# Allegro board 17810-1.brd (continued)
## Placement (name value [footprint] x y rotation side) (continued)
Q1801  2N7002KDW-1-GP  [SOT-363H44]  101.62 16.02 90 bottom
Q2001  PJT138KA-GP  [SOT-363H44]  150.49 27.25 180 bottom
Q2408  2N7002K-2-GP  [SOT23DGS2D4H44]  191.49 39.11 0 bottom
Q2414  2N7002K-2-GP  [SOT23DGS2D4H44]  187.27 35.12 180 bottom
Q2415  2N7002K-2-GP  [SOT23DGS2D4H44]  190.93 35.42 90 bottom
Q2416  2N7002KDW-1-GP  [SOT-363H44]  180.95 47.54 0 top
Q2417  2N7002K-2-GP  [SOT23DGS2D4H44]  188.64 9.87 180 bottom
Q2503  2N7002KDW-1-GP  [SOT-363H44]  141.2 10.43 270 bottom
Q2601  2N7002KDW-1-GP  [SOT-363H44]  134.77 32.76 90 bottom
Q2602  2N7002K-2-GP  [SOT23DGS2D4H44]  142.64 23.69 180 bottom
Q2603  PMBS3904-1-GP  [SOT-23-10H44]  49.5 96.38 90 bottom
Q2605  2N7002KDW-GP  [SOT-363H44]  196.04 36.64 0 bottom
Q2701  2N7002K-2-GP  [SOT23DGS2D4H44]  21.64 29.96 270 bottom
Q2702  DMG3415U-GP  [SOT23DGS2D4H48]  21.64 26.41 90 bottom
Q3701  2N7002K-2-GP  [SOT23DGS2D4H44]  23.42 98.09 0 top
Q5704  2N7002KDW-1-GP  [SOT-363H44]  18.62 61.71 0 bottom
Q6401  LDTA144VLT1G-GP  [SOT23CBE2D4H44]  53.39 7.84 270 bottom
Q6402  LDTA144VLT1G-GP  [SOT23CBE2D4H44]  69.62 15.1 270 bottom
Q6403  PJA138KA-GP  [SOT23DGS2D4H44]  177.54 48.45 270 top
Q6501  DMN3404L-7-1-GP  [SOT23DGS2D4H44]  113.28 10.3 270 bottom
Q6502  DMG3415U-GP  [SOT23DGS2D4H48]  141.63 14.22 270 bottom
Q6503  2N7002K-2-GP  [SOT23DGS2D4H44]  141.27 18.25 180 bottom
Q6504  2N7002KDW-1-GP  [SOT-363H44]  136.19 21.86 270 bottom
Q6505  LDTA144VLT1G-GP  [SOT23CBE2D4H44]  147.22 21.51 90 bottom
Q7001  2N7002KDW-1-GP  [SOT-363H44]  148 11.4 180 bottom
Q9102  DMP2130L-7-GP  [SOT23DGS2D4H48]  28.67 19.52 90 bottom
Q9104  SSM3K15AMFV-GP-U  [SOT723DGS1D2H22]  33.83 22.83 90 top
R401  1KR2J-1-GP  [R402H16]  131.14 76.98 270 bottom
R402  51R2J-2-GP  [R402H16]  133.02 70.45 180 bottom
R403  499R2F-2-GP  [R402H16]  130.58 76.14 90 bottom
R404  100KR2J-1-GP  [R402H16]  121.64 13.99 90 bottom
R406  51R2J-2-GP  [R402H16]  131.14 72.33 270 bottom
R407  51R2J-2-GP  [R402H16]  123.9 69.03 0 top
R408  51R2J-2-GP  [R402H16]  131.16 67.1 270 bottom
R409  51R2J-2-GP  [R402H16]  131.47 66.29 270 bottom
R410  -  [0R0402-PAD]  120.32 12.67 0 bottom
R412  49D9R2F-GP  [R402H16]  93.9 51.45 270 top
R413  49D9R2F-GP  [R402H16]  94.38 53.18 270 top
R414  49D9R2F-GP  [R402H16]  120.9 74.85 180 top
R415  49D9R2F-GP  [R402H16]  120.9 73.14 180 top
R416  51R2J-2-GP  [R402H16]  131.14 68.72 270 bottom
R417  1KR2J-1-GP  [R402H16]  131.16 67.91 270 bottom
R419  1KR2J-1-GP  [R402H16]  133.45 75.23 90 bottom
R421  51R2J-2-GP  [R402H16]  131.19 70.7 270 bottom
R422  51R2J-2-GP  [R402H16]  131.47 65.47 270 bottom
R423  51R2J-2-GP  [R402H16]  131.14 71.52 270 bottom
R501  121R2F-GP  [R402H16]  94.36 54.91 270 top
R502  80D6R2F-L-GP  [R402H16]  94.36 54.02 270 top
R503  100R2F-L1-GP-U  [R402H14]  93.9 52.32 270 top
R504  -  [0R0402-PAD]  88.44 18.25 270 top
R505  470R2F-GP  [R402H16]  88.44 16.35 90 top
R506  220KR2F-GP  [R402H16]  30.53 9.74 270 bottom
R601  49D9R2F-GP  [R402H16]  121.46 70.45 180 top
R602  -  [0R0402-PAD]  94.41 79.47 270 top
R603  100KR2J-1-GP  [R402H16]  133.48 76.06 270 bottom
R604  1KR2J-1-GP  [R402H16]  131.16 77.82 270 bottom
R605  1KR2J-1-GP  [R402H16]  122.32 76.9 0 top
R703  -  [0R0603-PAD]  123.7 44.64 0 top
R705  -  [0R0805-PAD]  94.38 57.09 0 top
R706  D0002R5J-GP-U  [R805H20]  119.3 64.99 180 top
R707  D0002R5J-GP-U  [R805H20]  119.23 60.98 180 top
R708  D0002R5J-GP-U  [R805H20]  112.32 60.93 180 top
R709  -  [0R0402-PAD]  133.45 71.75 270 bottom
R712  0R2J-2-GP  [R402H16]  121.46 66.54 180 top
R719  100R2F-L1-GP-U  [R402H14]  121.92 54.8 90 top
R720  100R2F-L1-GP-U  [R402H14]  121.92 55.57 270 top
R721  100R2F-L1-GP-U  [R402H14]  119.56 77.44 90 top
R722  100R2F-L1-GP-U  [R402H14]  120.98 77.11 0 top
R723  54D9R2F-L1-GP  [R402H16]  133.45 73.5 90 bottom
R726  100R2F-L1-GP-U  [R402H14]  133.48 72.64 90 bottom
R727  56R2J-4-GP  [R402H16]  133.45 74.36 90 bottom
R728  220R2J-L2-GP  [R402H16]  131.11 74.16 90 bottom
R732  -  [0R0402-PAD]  131.11 73.35 270 bottom
R734  100R2F-L1-GP-U  [R402H14]  121.49 49.75 180 top
R735  100R2F-L1-GP-U  [R402H14]  123.49 48.61 270 top
R801  24D9R2F-L-GP  [R402H16]  121.46 64.61 180 top
R802  10KR2J-3-GP  [R402H16]  119.1 28.77 180 bottom
R803  100KR2J-1-GP  [R402H16]  121.92 27.68 90 bottom
R804  0R2J-2-GP  [R402H16]  121.26 26.86 90 bottom
R1101  -  [0R1206-PAD]  93.01 16.73 0 bottom
R1102  -  [0R0603-PAD]  120.98 35.86 270 top
R1103  -  [0R0603-PAD]  108.68 37.81 90 top
R1104  -  [0R0603-PAD]  111.66 36.88 90 top
R1204  10KR2F-L1-GP  [R402H15]  68.38 22.44 90 top
R1205  -  [0R0402-PAD]  66.67 22.44 90 top
R1206  2R2F-GP  [R402H16]  72.62 48.04 90 top
R1208  10KR2F-L1-GP  [R402H15]  68.38 21.63 90 top
R1209  24D9R2F-L-GP  [R402H16]  72.6 49.81 90 top
R1210  -  [0R0402-PAD]  66.04 20.08 90 top
R1211  10KR2F-L1-GP  [R402H15]  62.3 44.34 270 top
R1212  -  [0R0402-PAD]  63.98 44.34 270 top
R1215  240R2F-1-GP  [R402H16]  64.08 52.59 0 top
R1216  SC2D2U10V3KX-L-GP  [C603H36]  50.95 26.74 270 top
R1302  10KR2F-L1-GP  [R402H15]  54.84 22.52 90 top
R1303  -  [0R0402-PAD]  53.11 22.52 90 top
R1305  2R2F-GP  [R402H16]  50.85 43.15 270 top
R1306  10KR2F-2-GP  [R402H16]  55.8 24.07 90 top
R1307  0R2J-L-GP  [R402H15]  54.05 24.1 270 top
R1309  24D9R2F-L-GP  [R402H16]  50.6 45.05 270 top
R1310  10KR2F-L1-GP  [R402H15]  48.46 46.4 180 top
R1311  -  [0R0402-PAD]  49.76 45.94 90 top
R1312  240R2F-1-GP  [R402H16]  51.31 55.87 270 top
R1501  100R2F-L1-GP-U  [R402H14]  123.32 42.51 270 top
R1502  200R2F-L-GP  [R402H16]  108.7 36.8 90 top
R1503  10KR2J-3-GP  [R402H16]  129.84 39.39 90 bottom
R1603  113R2F-GP  [R402H16]  115.21 38.7 90 top
R1604  100R2F-L1-GP-U  [R402H14]  122.6 38.8 90 top
R1606  10KR2J-3-GP  [R402H16]  120.67 28.24 0 bottom
R1607  10KR2J-3-GP  [R402H16]  87.02 21.84 90 top
R1608  10KR2J-3-GP  [R402H16]  119.86 28.24 0 bottom
R1701  10KR2J-3-GP  [R402H16]  117.42 43.25 90 top
R1702  1KR2J-1-GP  [R402H16]  150.42 19.02 270 top
R1704  -  [0R0402-PAD]  100.38 18.25 270 bottom
R1706  -  [0R0402-PAD]  102.08 18.25 90 bottom
R1707  10KR2J-3-GP  [R402H16]  59.74 15.46 180 bottom
R1708  -  [0R0402-PAD]  111.1 23.54 180 bottom
R1711  -  [0R0603-PAD]  58.72 15.84 180 bottom
R1713  -  [0R0402-PAD]  113.56 23.74 90 bottom
R1714  10KR2J-3-GP  [R402H16]  133.04 77.33 0 bottom
R1715  100KR2J-1-GP  [R402H16]  114.91 23.18 180 bottom
R1716  100KR2F-L1-GP  [R402H16]  106.6 93.82 180 bottom
R1717  100KR2J-1-GP  [R402H16]  123.47 37.13 270 top
R1718  0R2J-2-GP  [R402H16]  103.78 18.25 270 bottom
R1719  47KR2F-GP  [R402H16]  105.84 93.82 0 bottom
R1720  -  [0R0402-PAD]  150.42 18 90 top
R1724  0R6J-L-GP  [R1206H26]  97.69 14.95 0 bottom
R1726  10KR2J-3-GP  [R402H16]  150.85 13.48 270 bottom
R1727  100KR2J-1-GP  [R402H16]  152.55 13.48 270 bottom
R1728  -  [0R0402-PAD]  151.56 15.84 270 top
R1730  330KR2J-L1-GP  [R402H16]  96.24 22.62 180 top
R1731  20KR2J-L2-GP  [R402H16]  110.75 39.67 180 top
R1732  0R2J-2-GP  [R402H16]  60.5 15.46 0 bottom
R1737  100KR2J-1-GP  [R402H16]  152.8 20.13 90 top
R1739  10KR2J-3-GP  [R402H16]  109.27 25.37 270 bottom
R1802  1MR2J-1-GP  [R402H16]  131.93 50.72 180 bottom
R1803  2K7R2F-GP  [R402H16]  119.38 49.06 0 top
R1804  0R2J-2-GP  [R402H16]  131.16 52.39 0 bottom
R1805  0R2J-2-GP  [R402H16]  131.16 50.72 0 bottom
R1806  15R2F-2-GP  [R402H16]  89.08 30.19 0 top
R1807  0R2J-2-GP  [R402H16]  94.28 49.37 90 top
R1808  0R2J-2-GP  [R402H16]  115.24 18.76 180 bottom
R1811  10R2F-L-GP  [R402H14]  94.44 28.64 90 top
R1812  -  [0R0402-PAD]  94.44 27.65 90 top
R1815  10MR2J-L-GP  [R402H16]  99.52 22.85 180 bottom
R1818  8K2R2F-1-GP  [R402H16]  106.98 25.24 0 bottom
R1820  10KR2J-3-GP  [R402H16]  97.94 22.37 180 top
R1821  10KR2J-3-GP  [R402H16]  97.1 22.39 180 top
R1822  1KR2J-1-GP  [R402H16]  113.26 25.01 180 bottom
R1823  1KR2J-1-GP  [R402H16]  112.01 25.14 90 bottom
R1824  1KR2J-1-GP  [R402H16]  94.89 33.8 180 top
R1825  1KR2J-1-GP  [R402H16]  94.46 32.53 90 top
R1826  0R2J-2-GP  [R402H16]  107.47 32.43 270 bottom
R1827  10KR2J-3-GP  [R402H16]  94.41 41.62 90 top
R1828  10KR2J-3-GP  [R402H16]  94.41 39.34 90 top
R1836  2K2R2J-2-GP  [R402H16]  114.07 25.44 180 bottom
R1837  150KR2J-GP  [R402H16]  108.76 38.83 90 top
R1901  200R2F-L-GP  [R402H16]  115.28 39.46 90 top
R1908  -  [0R0402-PAD]  93.62 46.83 90 top
R1909  1KR2J-1-GP  [R402H16]  91.11 49.5 90 top
R1912  10KR2J-3-GP  [R402H16]  124.89 21.43 0 top
R1913  10KR2J-3-GP  [R402H16]  123.75 22.19 0 top
R1914  10KR2J-3-GP  [R402H16]  115.16 19.68 0 top
R1915  10KR2J-3-GP  [R402H16]  114.37 19.68 180 top
R1916  10KR2J-3-GP  [R402H16]  113.59 20.92 90 top
R1917  10KR2J-3-GP  [R402H16]  113.08 22.19 0 top
R1918  10KR2J-3-GP  [R402H16]  109.52 21.05 270 top
R1919  10KR2J-3-GP  [R402H16]  111.68 22.55 270 top
R1920  10KR2J-3-GP  [R402H16]  109.17 22.32 0 top
R1921  10KR2J-3-GP  [R402H16]  108.35 22.32 180 top
R2001  10KR2J-3-GP  [R402H16]  148.69 23.99 270 bottom
R2003  0R2J-2-GP  [R402H16]  110.67 27.4 0 bottom
R2004  0R2J-2-GP  [R402H16]  109.85 27.58 0 bottom
R2005  10KR2J-3-GP  [R402H16]  112.09 29.81 180 bottom
R2006  1KR2J-1-GP  [R402H16]  94.36 37.05 90 top
R2007  1KR2J-1-GP  [R402H16]  109.78 20.36 0 bottom
R2008  10KR2J-3-GP  [R402H16]  110.31 29.02 90 bottom
R2009  10KR2J-3-GP  [R402H16]  113.36 32.12 270 bottom
R2010  10KR2J-3-GP  [R402H16]  112.9 30.88 0 bottom
R2019  1KR2J-1-GP  [R402H16]  110.54 20.36 180 bottom
R2020  0R2J-2-GP  [R402H16]  117.17 23.97 180 bottom
R2021  0R2J-2-GP  [R402H16]  118.03 23.97 180 bottom
R2023  0R2J-2-GP  [R402H16]  94.49 23.28 90 top
R2024  0R2J-2-GP  [R402H16]  94.79 24.1 90 top
R2025  0R2J-2-GP  [R402H16]  94.84 25.72 90 top
R2026  0R2J-2-GP  [R402H16]  94.79 24.91 90 top
R2027  0R2J-2-GP  [R402H16]  94.84 26.53 90 top
R2028  0R2J-2-GP  [R402H16]  102.28 20.03 180 bottom
R2029  10KR2J-3-GP  [R402H16]  109.4 30.24 0 bottom
R2030  10KR2J-3-GP  [R402H16]  108.63 30.88 180 bottom
R2031  100KR2J-1-GP  [R402H16]  91.24 25.37 270 top
R2032  100KR2J-1-GP  [R402H16]  91.24 26.25 270 top
R2033  100KR2J-1-GP  [R402H16]  91.24 27.02 270 top
R2034  100KR2J-1-GP  [R402H16]  103.55 21.3 90 top
R2035  100KR2J-1-GP  [R402H16]  91.24 27.78 270 top
R2036  100KR2J-1-GP  [R402H16]  91.24 28.54 270 top
R2040  10KR2J-3-GP  [R402H16]  114.07 27.12 0 bottom
R2041  10KR2J-3-GP  [R402H16]  109.02 20.36 0 bottom
R2042  10KR2J-3-GP  [R402H16]  122.81 24.38 180 bottom
R2043  10KR2J-3-GP  [R402H16]  108.25 20.03 0 bottom
R2044  10KR2J-3-GP  [R402H16]  112.11 31.67 0 bottom
R2045  10KR2J-3-GP  [R402H16]  121.59 22.7 90 top
R2046  10KR2J-3-GP  [R402H16]  114.73 31.59 0 bottom
R2047  10KR2J-3-GP  [R402H16]  115.49 31.59 0 bottom
R2048  51KR2J-1-GP  [R402H16]  110.92 30.24 0 bottom
R2049  51KR2J-1-GP  [R402H16]  110.16 30.24 0 bottom
R2050  10KR2J-3-GP  [R402H16]  148.59 25.21 180 bottom
R2055  150KR2J-GP  [R402H16]  107.87 30.88 0 bottom
R2056  20KR2J-L2-GP  [R402H16]  108.68 32.76 0 bottom
R2101  -  [0R0402-PAD]  69.9 18.51 270 top
R2102  0R2J-2-GP  [R402H16]  67.61 17.49 90 top
R2106  -  [0R0603-PAD]  76.43 16.93 0 top
R2107  -  [0R0603-PAD]  120.11 38.55 90 top
R2108  -  [0R0603-PAD]  115.11 42.19 0 top
R2109  -  [0R0603-PAD]  134.8 41.88 270 bottom
R2110  -  [0R0603-PAD]  134.8 44.42 270 bottom
R2111  -  [0R0603-PAD]  134.8 43.15 270 bottom
R2201  1MR2J-1-GP  [R402H16]  131.8 36.08 180 bottom
R2202  0R2J-2-GP  [R402H16]  130.58 36.44 90 bottom
R2203  0R2J-2-GP  [R402H16]  130.58 35.65 90 bottom
R2402  -  [0R0402-PAD]  177.42 31.49 90 top
R2414  4K7R2J-2-GP  [R402H16]  163.98 17.47 0 top
R2415  10KR2J-3-GP  [R402H16]  184.96 28.69 180 bottom
R2417  100KR2J-1-GP  [R402H16]  190.5 41.37 270 bottom
R2418  0R2J-2-GP  [R402H16]  189.28 41.34 180 bottom
R2420  -  [0R0402-PAD]  198.37 44.16 90 bottom
R2421  330R2J-3-GP  [R402H16]  189.1 31.18 180 bottom
R2422  -  [0R0402-PAD]  185.6 41.9 90 bottom
R2423  -  [0R0402-PAD]  184.86 31.18 0 bottom
R2424  20KR2F-L-GP  [R402H16]  194.13 44.16 180 bottom
R2425  0R2J-2-GP  [R402H16]  198.8 26.51 0 top
R2426  330R2J-3-GP  [R402H16]  191.92 26.76 90 bottom
R2429  10KR2J-3-GP  [R402H16]  189.25 38.04 180 bottom
R2430  10KR2J-3-GP  [R402H16]  187.27 41.49 90 bottom
R2431  10KR2J-3-GP  [R402H16]  198.75 42.13 270 bottom
R2432  1KR2J-1-GP  [R402H16]  186.18 29.18 270 bottom
R2434  100KR2J-1-GP  [R402H16]  200.2 34.94 90 bottom
R2435  -  [0R0402-PAD]  164.13 32.22 270 top
R2436  100KR2J-1-GP  [R402H16]  185.09 34.54 0 bottom
R2437  43R2J-GP  [R402H16]  178.79 33.54 270 top
R2441  100KR2F-L1-GP  [R402H16]  185.82 31.36 0 bottom
R2442  64K9R2F-1-GP  [R402H16]  185.06 32.86 180 bottom
R2443  49K9R2F-L-GP  [R402H16]  191.69 32.81 180 bottom
R2444  100KR2F-L1-GP  [R402H16]  190.93 32.81 0 bottom
R2445  -  [0R0402-PAD]  191.82 28.29 90 bottom
R2446  -  [0R0603-PAD]  201.67 33.65 270 top
R2447  -  [0R0402-PAD]  198.96 35.02 0 bottom
R2448  10KR2F-2-GP  [R402H16]  195.43 44.54 270 bottom
R2449  100KR2J-1-GP  [R402H16]  184.94 43.91 180 bottom
R2450  100KR2J-1-GP  [R402H16]  186.15 43.45 270 bottom
R2451  100KR2J-1-GP  [R402H16]  190.17 31.18 180 bottom
R2454  100KR2J-1-GP  [R402H16]  191.26 9.01 270 bottom
R2456  115KR2F-GP  [R402H16]  198.6 39.95 0 bottom
R2459  -  [0R0402-PAD]  197.94 36.29 0 bottom
R2461  -  [0R0402-PAD]  193.65 36.75 270 bottom
R2462  -  [0R0402-PAD]  187.83 43.45 90 bottom
R2463  1KR2J-1-GP  [R402H16]  190.8 10.99 180 bottom
R2464  1KR2J-1-GP  [R402H16]  191.26 9.77 90 bottom
R2470  -  [0R0402-PAD]  198.75 41.22 270 bottom
R2471  0R2J-2-GP  [R402H16]  198.75 42.89 270 bottom
R2472  -  [0R0402-PAD]  192.02 30.57 90 bottom
R2473  10KR2J-3-GP  [R402H16]  186.66 26.76 90 bottom
R2474  -  [0R0402-PAD]  179.63 52.67 0 top
R2475  -  [0R0402-PAD]  176.2 54.32 0 top
R2476  0R2J-2-GP  [R402H16]  166.9 45.2 180 top
R2477  0R2J-2-GP  [R402H16]  166.14 45.2 180 top
R2480  100KR2J-1-GP  [R402H16]  163.55 16.15 90 top
R2489  100KR2J-1-GP  [R402H16]  186.56 32.58 270 bottom
R2496  100KR2J-1-GP  [R402H16]  193.22 35.07 180 bottom
R2501  4K7R2J-2-GP  [R402H16]  120.06 22.19 90 bottom
R2503  10R2F-L-GP  [R402H14]  123.19 16.15 0 bottom
R2504  10MR2J-L-GP  [R402H16]  143.81 10.76 270 bottom
R2505  10R2F-L-GP  [R402H14]  121.26 17.7 90 bottom
R2506  10R2F-L-GP  [R402H14]  121.26 18.46 90 bottom
R2507  10R2F-L-GP  [R402H14]  120.95 21.17 270 bottom
R2508  10R2F-L-GP  [R402H14]  122.73 19.65 270 bottom
R2509  100KR2J-1-GP  [R402H16]  139.9 10.84 0 top
R2510  0R2J-2-GP  [R402H16]  151.49 20.91 90 bottom
R2515  -  [0R0402-PAD]  123.11 13.99 180 bottom
R2517  47KR2F-GP  [R402H16]  150.24 21.35 0 bottom
R2601  0R2J-2-GP  [R402H16]  141.68 21.35 270 bottom
R2602  -  [0R0402-PAD]  144.17 20.97 180 bottom
R2603  7K5R2F-1-GP  [R402H16]  133.83 24.2 180 bottom
R2604  7K5R2F-1-GP  [R402H16]  140.46 22.52 180 bottom
R2607  10KR2J-3-GP  [R402H16]  143.89 19.75 270 bottom
R2608  27KR2F-L-GP  [R402H16]  122.35 28.92 0 bottom
R2609  10R2F-L-GP  [R402H14]  121.54 28.92 0 bottom
R2610  NTC-100K-8-GP  [NTC-603H38]  122.86 31.72 180 bottom
R2611  -  [0R0402-PAD]  194.36 40.81 90 bottom
R2612  -  [0R0402-PAD]  149.02 77.94 90 top
R2613  -  [0R0402-PAD]  149.02 77.05 90 top
R2614  -  [0R0402-PAD]  149.02 76.17 90 top
R2615  0R2J-2-GP  [R402H16]  144.93 20.97 180 bottom
R2702  -  [0R0805-PAD]  29.49 15.04 90 bottom
R2703  -  [0R0603-PAD]  24.69 11.7 180 bottom
R2704  -  [0R0805-PAD]  29.49 16.84 90 bottom
R2705  0R2J-2-GP  [R402H16]  25.04 22.83 270 top
R2706  -  [0R0805-PAD]  20.32 10.46 180 bottom
R2708  -  [0R0402-PAD]  29.94 14.37 270 top
R2709  200KR2F-L-GP  [R402H16]  29.01 11.27 270 top
R2710  0R2J-2-GP  [R402H16]  25.04 23.59 270 top
R2711  100KR2J-1-GP  [R402H16]  19.12 12.82 0 bottom
R2713  -  [0R0402-PAD]  25.04 22.06 270 top
R2714  100R2F-L1-GP-U  [R402H14]  33.15 15.51 180 top
R2716  100R2F-L1-GP-U  [R402H14]  30.55 16.43 90 top
R2717  2K2R2J-2-GP  [R402H16]  26.52 13 0 bottom
R2718  -  [0R0402-PAD]  32.89 19.12 270 top
R2719  -  [0R0402-PAD]  30.55 19.96 270 top
R2720  -  [0R0402-PAD]  30.25 18.41 270 top
R2722  100KR2J-1-GP  [R402H16]  29.01 12.16 270 top
R2723  -  [0R0402-PAD]  20.52 15.54 0 bottom
R2724  -  [0R0402-PAD]  24.69 19.45 0 bottom
R2725  -  [0R0402-PAD]  27.35 11.47 180 top
R2726  10KR2J-3-GP  [R402H16]  19.3 28.85 0 bottom
R2727  20KR2J-L2-GP  [R402H16]  18.46 28.85 180 bottom
R2728  100KR2J-1-GP  [R402H16]  30.4 12.67 0 top
R2731  -  [0R0805-PAD]  28.57 26.31 0 top
R2732  0R2J-2-GP  [R402H16]  30.25 17.64 90 top
R2905  -  [0R0402-PAD]  18.03 24.53 270 bottom
R2906  -  [0R0603-PAD]  16.23 15.08 0 top
R2907  -  [0R0603-PAD]  17.02 19.93 270 top
R2908  10R2F-L-GP  [R402H14]  16.97 17.34 90 bottom
R2909  -  [0R0603-PAD]  20.24 22.75 270 top
R2910  10R2F-L-GP  [R402H14]  16.97 21.56 90 bottom
R2911  -  [0R0603-PAD]  17.5 15.08 0 top
R2912  2K2R2J-2-GP  [R402H16]  16.97 18.1 270 bottom
R2913  2K2R2J-2-GP  [R402H16]  16.97 23.44 90 bottom
R2919  10KR2J-3-GP  [R402H16]  16.97 18.99 270 bottom
R2920  10KR2J-3-GP  [R402H16]  16.97 19.85 270 bottom
R2921  -  [0R0402-PAD]  16.97 22.62 90 bottom
R2922  -  [0R0402-PAD]  16.97 16.58 270 bottom
R2923  -  [0R0603-PAD]  17.04 21.23 90 top
R3401  -  [0R0402-PAD]  19.48 42.51 90 bottom
R3402  10KR2J-3-GP  [R402H16]  19.35 48.86 180 bottom
R3403  20KR2F-L-GP  [R402H16]  26.39 48.43 270 top
R3404  22K1R2F-L-GP  [R402H16]  27.13 46.98 270 top
R3405  10KR2J-3-GP  [R402H16]  20.88 42.13 0 bottom
R3406  10KR2J-3-GP  [R402H16]  18.21 42.13 0 bottom
R3501  100KR2J-1-GP  [R402H16]  22.66 35.14 180 bottom
R3605  -  [0R0402-PAD]  22.17 53.97 270 top
R3606  -  [0R0402-PAD]  22.17 54.78 270 top
R3609  -  [0R0402-PAD]  23.47 51.27 270 top
R3610  -  [0R0402-PAD]  23.47 52.09 270 top
R3611  -  [0R0402-PAD]  22.6 31.72 270 top
R3612  -  [0R0402-PAD]  23.65 29.51 270 top
R3613  -  [0R0402-PAD]  23.65 30.32 270 top
R3614  -  [0R0402-PAD]  22.6 32.48 270 top
R3706  1MR2J-1-GP  [R402H16]  22.78 39.46 0 top
R3707  2K2R2J-2-GP  [R402H16]  29.51 37.15 90 top
R3724  4K7R2J-2-GP  [R402H16]  28.12 33.37 180 top
R3725  10KR2F-2-GP  [R402H16]  34.21 36.8 180 top
R3726  10KR2F-2-GP  [R402H16]  31.01 33.52 270 top
R3727  0R2J-2-GP  [R402H16]  23.93 42.26 270 top
R3728  0R2J-2-GP  [R402H16]  23.29 40.73 90 bottom
R3729  0R2J-2-GP  [R402H16]  32.94 37.3 90 top
R3730  100KR2F-L1-GP  [R402H16]  31.01 31.74 270 top
R3731  0R2J-2-GP  [R402H16]  29.97 35.91 180 top
R3732  0R2J-2-GP  [R402H16]  32.18 50.13 90 top
R3733  0R2J-2-GP  [R402H16]  29.77 50.13 270 top
R3734  100KR2J-1-GP  [R402H16]  26.47 36.29 180 top
R3735  2MR2-GP  [R402H16]  32.94 38.07 90 top
R3736  0R2J-2-GP  [R402H16]  24.86 43.92 180 top
R3737  0R3J-0-U-GP  [R603H22]  23.54 41.11 90 top
R3738  10KR2J-3-GP  [R402H16]  25.96 98.01 180 top
R3739  100KR2J-1-GP  [R402H16]  26.21 95.98 90 top
R3750  30KR2F-GP  [R402H16]  37.51 41.24 270 top
R3751  3KR2F-GP  [R402H16]  35.74 40.73 270 top
R3752  30KR2F-GP  [R402H16]  37.51 42.13 270 top
R3753  10KR2F-L1-GP  [R402H15]  35.74 42.13 270 top
R3801  100KR2J-1-GP  [R402H16]  33.04 63.97 90 top
R3802  100KR2J-1-GP  [R402H16]  34.72 63.97 270 top
R3814  0R2J-2-GP  [R402H16]  40.82 62.96 270 top
R3816  0R2J-2-GP  [R402H16]  40.82 63.85 270 top
R3818  10KR2J-3-GP  [R402H16]  29.01 61.31 90 top
R3821  4K7R2J-2-GP  [R402H16]  29.01 60.42 90 top
R3830  2MR2F-GP  [R402H16]  17.88 97.07 180 top
R3831  2MR2F-GP  [R402H16]  17.88 95.39 0 top
R3832  -  [0R0402-PAD]  20.88 92.65 270 top
R3833  -  [0R0402-PAD]  20.88 93.46 270 top
R3834  -  [0R0402-PAD]  21.39 94.68 270 top
R3835  -  [0R0402-PAD]  21.39 95.5 270 top
R3836  -  [0R0402-PAD]  19.99 98.67 270 top
R3837  -  [0R0402-PAD]  19.99 97.86 270 top
R3838  -  [0R0402-PAD]  17.19 99.94 270 top
R3839  -  [0R0402-PAD]  17.19 99.13 270 top
R3840  1KR2J-1-GP  [R402H16]  29.01 59.61 90 top
R3841  1KR2J-1-GP  [R402H16]  29.01 58.79 270 top
R3842  1KR2J-1-GP  [R402H16]  29.01 57.17 90 top
R3843  1KR2J-1-GP  [R402H16]  29.01 57.98 270 top
R3844  1KR2J-1-GP  [R402H16]  29.26 53.94 0 top
R3845  1KR2J-1-GP  [R402H16]  38.28 55.41 270 top
R3846  1KR2J-1-GP  [R402H16]  38.28 56.23 90 top
R3847  1KR2J-1-GP  [R402H16]  27.68 53.94 180 top
R3849  0R2J-2-GP  [R402H16]  41.71 64.74 270 top
R3852  1KR2J-1-GP  [R402H16]  28.47 53.94 180 top
R3853  0R2J-2-GP  [R402H16]  44.88 32.6 90 top
R3854  0R2J-2-GP  [R402H16]  42.09 32.6 90 top
R3855  0R2J-2-GP  [R402H16]  38.78 40.35 0 top
R3856  0R2J-2-GP  [R402H16]  40.56 40.99 0 top
R3857  2R2F-GP  [R402H16]  36.63 38.95 90 top
R3858  2R2F-GP  [R402H16]  41.32 40.99 0 top
R3859  0R2J-2-GP  [R402H16]  36.63 38.07 270 top
R3860  0R2J-2-GP  [R402H16]  42.19 41.01 180 top
R3861  0R2J-2-GP  [R402H16]  37.36 36.47 270 top
R3862  0R2J-2-GP  [R402H16]  37.36 35.7 270 top
R3863  0R2J-2-GP  [R402H16]  45.72 37.13 180 top
R3864  0R2J-2-GP  [R402H16]  44.96 37.13 180 top
R3870  1KR2J-1-GP  [R402H16]  27.99 55.21 270 top
R3871  1KR2J-1-GP  [R402H16]  38.4 58.13 270 top
R3872  1KR2J-1-GP  [R402H16]  38.4 58.89 90 top
R3873  1KR2J-1-GP  [R402H16]  38.4 60.44 90 top
R3874  1KR2J-1-GP  [R402H16]  38.4 61.26 270 top
R4002  -  [0R0402-PAD]  163.9 99.91 180 bottom
R4005  1KR2J-1-GP  [R402H16]  161.8 100.55 90 bottom
R4006  20KR2F-L-GP  [R402H16]  116.89 19.93 270 bottom
R4009  10KR2J-3-GP  [R402H16]  116.76 17.77 270 bottom
R4010  0R2J-2-GP  [R402H16]  127.43 99.43 180 bottom
R4011  -  [0R0402-PAD]  161.26 101.77 180 bottom
R4012  0R2J-2-GP  [R402H16]  126.97 102.51 90 top
R4013  0R2J-2-GP  [R402H16]  130.78 101.72 270 bottom
R4014  0R2J-2-GP  [R402H16]  130.78 102.48 270 bottom
R4017  -  [0R0402-PAD]  87.65 89.55 90 top
R4024  -  [0R0402-PAD]  103.96 16.81 0 bottom
R4029  -  [0R0402-PAD]  158.72 104.69 180 bottom
R4030  -  [0R0402-PAD]  160.5 104.69 180 bottom
R4031  100KR2J-1-GP  [R402H16]  161.26 104.69 180 bottom
R4032  100KR2J-1-GP  [R402H16]  157.83 104.69 180 bottom
R4033  0R2J-2-GP  [R402H16]  159.61 104.69 180 bottom
R4036  -  [0R0402-PAD]  111.4 15.51 180 bottom
R4038  -  [0R0402-PAD]  112.16 15.51 180 bottom
R4042  -  [0R0402-PAD]  98.22 91.66 90 top
R4045  -  [0R1206-PAD]  93.57 86.15 0 top
R4101  -  [0R0805-PAD]  112.83 13 270 bottom
R4301  -  [0R0402-PAD]  170.23 25.11 0 top
R4303  1KR2F-3-GP  [R402H16]  24.81 88.36 90 top
R4462  0R2J-2-GP  [R402H16]  137.46 29.68 270 top
R5411  4K7R2J-2-GP  [R402H16]  20.62 69.05 270 bottom
R5412  4K7R2J-2-GP  [R402H16]  21.89 68.11 0 bottom
R5413  4K7R2J-2-GP  [R402H16]  23.9 60.6 0 top
R5414  4K7R2J-2-GP  [R402H16]  23.11 60.6 0 top
R5415  4K7R2J-2-GP  [R402H16]  23.04 70.45 180 bottom
R5416  4K7R2J-2-GP  [R402H16]  22.66 68.11 0 bottom
R5417  4K7R2J-2-GP  [R402H16]  23.8 70.45 180 bottom
R5418  4K7R2J-2-GP  [R402H16]  23.93 68.11 0 bottom
R5419  4K7R2J-2-GP  [R402H16]  24.56 70.45 180 bottom
R5420  4K7R2J-2-GP  [R402H16]  18.34 67.28 180 bottom
R5501  -  [0R0402-PAD]  64.18 89.5 0 top
R5502  0R2J-2-GP  [R402H16]  105.33 96.23 180 top
R5503  -  [0R0402-PAD]  100 95.04 90 top
R5507  0R3J-0-U-GP  [R603H22]  67.36 98.64 0 top
R5512  0R2J-2-GP  [R402H16]  109.9 97.88 270 bottom
R5513  0R3J-0-U-GP  [R603H22]  58.19 97.96 90 top
R5514  0R6J-L-GP  [R1206H26]  78.18 96.64 180 top
R5515  -  [0R0402-PAD]  91.87 101.31 270 top
R5516  0R3J-0-U-GP  [R603H22]  56.67 93.79 270 top
R5520  0R3J-0-U-GP  [R603H22]  54.3 93.01 270 top
R5540  -  [0R0402-PAD]  65.91 93.06 90 top
R5701  -  [0R0603-PAD]  17.88 69.89 90 top
R5702  180R2J-1-GP  [R402H16]  18.72 66.13 0 top
R5703  180R2J-1-GP  [R402H16]  18.72 63.21 0 top
R5704  180R2J-1-GP  [R402H16]  17.96 64.61 0 top
R5705  180R2J-1-GP  [R402H16]  17.96 67.36 0 top
R5706  2K2R2J-2-GP  [R402H16]  21.89 60.6 180 top
R5707  2K2R2J-2-GP  [R402H16]  20.47 60.6 180 top
R5710  4D3KR2F-GP  [R402H16]  21.89 71.72 270 top
R5715  -  [0R0603-PAD]  24.43 58.39 180 top
R5716  0R3J-0-U-GP  [R603H22]  25.7 58.39 180 top
R5721  100KR2J-1-GP  [R402H16]  20.06 57.95 90 bottom
R5722  -  [0R0402-PAD]  17.96 64.58 0 bottom
R5723  -  [0R0402-PAD]  18.85 58.41 0 bottom
R6001  -  [0R0402-PAD]  182.93 25.11 270 top
R6002  -  [0R0402-PAD]  178.18 17.8 180 top
R6003  -  [0R0603-PAD]  176.81 20.84 90 top
R6005  0R2J-2-GP  [R402H16]  172.26 16.96 180 top
R6006  -  [0R0603-PAD]  172.01 20.11 180 top
R6007  0R2J-2-GP  [R402H16]  171.37 16.96 180 top
R6120  10KR2J-3-GP  [R402H16]  178.05 51.07 180 top
R6301  -  [0R0402-PAD]  200.86 15.76 180 top
R6302  -  [0R0603-PAD]  201.67 19.27 270 top
R6303  10KR2J-3-GP  [R402H16]  200.86 14.06 180 top
R6304  10KR2J-3-GP  [R402H16]  202.23 14.95 90 top
R6306  100KR2J-1-GP  [R402H16]  198.65 8.55 0 bottom
R6307  -  [0R0603-PAD]  202.11 10.51 180 top
R6308  -  [0R0402-PAD]  196.01 24.98 90 top
R6310  0R2J-2-GP  [R402H16]  192.23 14.19 270 bottom
R6401  499R2F-2-GP  [R402H16]  67.79 11.42 90 bottom
R6402  330R2J-3-GP  [R402H16]  52.68 4.28 0 bottom
R6403  -  [0R0402-PAD]  72.74 15.16 90 bottom
R6404  -  [0R0402-PAD]  180.26 49.72 270 top
R6501  0R3J-0-U-GP  [R603H22]  152.22 12.41 90 bottom
R6502  0R3J-0-U-GP  [R603H22]  138.73 21.43 180 bottom
R6503  100R3J-4-GP  [R603H22]  138.73 19.07 0 bottom
R6504  20KR2F-L-GP  [R402H16]  143.89 14.85 180 bottom
R6505  0R2J-2-GP  [R402H16]  134.54 22.19 90 top
R6506  0R2J-2-GP  [R402H16]  132.89 21.05 270 top
R6507  51KR2J-1-GP  [R402H16]  113.05 18.81 270 bottom
R6508  100KR2J-1-GP  [R402H16]  111.3 19.9 180 bottom
R6509  100KR2J-1-GP  [R402H16]  115.62 12.67 270 bottom
R6510  -  [0R0402-PAD]  137.46 19.9 90 top
R6511  10KR2J-3-GP  [R402H16]  128.19 3.9 180 top
R6512  -  [0R0402-PAD]  144.93 22.9 180 bottom
R6513  1KR2J-1-GP  [R402H16]  149.48 21.35 180 bottom
R6514  0R3J-0-U-GP  [R603H22]  138.73 15.84 0 bottom
R6801  0R2J-2-GP  [R402H16]  181.46 20.51 180 top
R6802  0R2J-2-GP  [R402H16]  160.37 12.77 270 top
R6803  0R2J-2-GP  [R402H16]  167.94 12.03 90 top
R6804  0R2J-2-GP  [R402H16]  167.94 12.79 90 top
R6805  0R2J-2-GP  [R402H16]  165.4 12.03 90 top
R6806  0R2J-2-GP  [R402H16]  165.4 12.79 90 top
R6807  0R2J-2-GP  [R402H16]  182.22 21.28 180 top
R6808  0R2J-2-GP  [R402H16]  160.37 12.01 270 top
R6809  0R2J-2-GP  [R402H16]  155.88 12.54 180 top
R6810  0R2J-2-GP  [R402H16]  155.12 12.54 180 top
R7001  100KR2J-1-GP  [R402H16]  16.25 83.4 180 top
R7002  0R2J-2-GP  [R402H16]  120.06 7.84 0 bottom
R7003  -  [0R0402-PAD]  120.06 9.62 180 bottom
R7004  -  [0R0402-PAD]  176.71 40.35 270 top
R7005  10KR2J-3-GP  [R402H16]  177.8 45.56 270 top
R7006  10KR2J-3-GP  [R402H16]  179.63 44.92 180 top
R7007  -  [0R0402-PAD]  177.8 44.67 90 top
R7008  -  [0R0402-PAD]  118.92 13.3 90 bottom
R7009  -  [0R0402-PAD]  116.58 20.29 90 top
R7010  -  [0R0402-PAD]  145.97 13.55 270 bottom
R7011  100KR2J-1-GP  [R402H16]  15.49 84.22 180 top
R7012  -  [0R0402-PAD]  118.29 20.29 270 top
R7013  -  [0R0402-PAD]  147.42 14.32 90 bottom
R7018  100KR2J-1-GP  [R402H16]  145.95 10.91 180 bottom
R9101  0R2J-2-GP  [R402H16]  46.02 24.73 0 top
R9102  0R2J-2-GP  [R402H16]  47.04 24.73 0 top
R9103  0R2J-2-GP  [R402H16]  44.75 24.35 90 top
R9119  10KR2J-3-GP  [R402H16]  42.09 23.59 180 top
R9120  10KR2J-3-GP  [R402H16]  31.67 27.78 270 top
R9129  100R2F-L1-GP-U  [R402H14]  32.82 21.17 90 top
R9130  0R2J-L-GP  [R402H15]  43.74 27.52 90 top
R9131  10KR2J-3-GP  [R402H16]  31.67 22.06 270 top
R9132  33R2J-2-GP  [R402H16]  78.05 20.24 270 top
R9133  0R2J-L-GP  [R402H15]  35.61 23.46 0 top
R9134  33R2J-2-GP  [R402H16]  78.05 19.47 270 top
R9136  0R2J-L-GP  [R402H15]  36.88 22.95 90 top
R9138  0R2J-L-GP  [R402H15]  31.67 23.59 270 top
R9139  33R2J-2-GP  [R402H16]  78.05 21 270 top
R9140  10KR2J-3-GP  [R402H16]  43.74 28.41 270 top
R9141  10KR2J-3-GP  [R402H16]  36.37 32.99 180 top
R9142  0R2J-L-GP  [R402H15]  43.74 31.33 90 top
R9143  0R2J-L-GP  [R402H15]  33.7 29.94 180 top
R9144  0R2J-L-GP  [R402H15]  34.97 32.1 90 top
R9145  0R2J-L-GP  [R402H15]  31.16 25.75 0 top
R9146  0R2J-L-GP  [R402H15]  30.28 25.75 0 top
R9147  0R2J-L-GP  [R402H15]  38.78 23.97 90 top
R9148  10KR2J-3-GP  [R402H16]  37.77 33.24 180 top
R9149  0R2J-L-GP  [R402H15]  43.74 30.19 270 top
RN801  SRN2K2J-1-GP  [ARES2H16]  107.36 98.14 270 bottom
RN803  SRN2K2J-1-GP  [ARES2H16]  120.04 24.93 180 bottom
RN1201  SRN1KJ-7-GP  [SMD-ARES4H18]  72.66 45.19 0 top
RN1301  SRN1KJ-7-GP  [SMD-ARES4H18]  50.78 40.32 0 top
RN1601  SRN10KJ-6-GP  [ARES8-CN24-MUH20]  138.63 46.93 90 top
RN1602  SRN0J-6-GP  [SMD-ARES4H20]  115.87 21.68 90 top
RN1703  SRN10KJ-5-GP  [ARES2H18]  100.84 20.06 0 bottom
RN1704  SRN10KJ-6-GP  [ARES8-CN24-MUH20]  105.92 19.57 180 bottom
RN1801  SRN20KJ-1-GP  [SMD-ARES4H20]  74.47 18.51 180 top
RN1802  SRN1KJ-7-GP  [SMD-ARES4H18]  94.28 30.6 180 top
RN1803  SRN10J-1-GP  [ARES8-CN24-UH18]  91.92 30.67 0 top
RN1806  SRN15J-GP  [ARES8-CN24-MUH20]  90.96 42.36 180 top
RN1807  SRN2K2J-4-GP  [ARES8-CN24-UH20]  112.49 26.76 180 bottom
RN1810  SRN10KJ-5-GP  [ARES2H18]  102.03 15.71 270 top
RN1811  SRN2K2J-1-GP  [ARES2H16]  103.94 16.86 90 top
RN1812  SRN10KJ-5-GP  [ARES2H18]  94.41 40.48 270 top
RN1813  SRN10KJ-5-GP  [ARES2H18]  94.41 38.19 270 top
RN1902  SRN33J-5-GP-U  [SMD-ARES4H18]  91.97 48.25 270 top
RN2007  SRN1KJ-7-GP  [SMD-ARES4H18]  118.11 26.92 0 bottom
RN2008  SRN2K2J-1-GP  [ARES2H16]  118.26 31.59 0 bottom
RN2009  SRN10KJ-5-GP  [ARES2H18]  117.19 37.56 90 top
RN2402  SRN4K7J-8-GP  [SMD-ARES4H18]  170.61 32.99 90 top
RN2403  SRN10KJ-6-GP  [ARES8-CN24-MUH20]  178.93 28.46 270 top
RN2404  SRN10KJ-6-GP  [ARES8-CN24-MUH20]  173.28 29.68 180 top
RN2405  SRN100KJ-5-GP  [ARES8-CN24H20]  172.13 39.46 90 top
RN2407  SRN10KJ-5-GP  [ARES2H18]  171.25 41.62 90 top
RN2409  SRN100KJ-5-GP  [ARES8-CN24H20]  192.48 44.11 180 bottom
RN2410  SRN100KJ-5-GP  [ARES8-CN24H20]  172.13 35.65 270 top
RN2411  SRN100KJ-5-GP  [ARES8-CN24H20]  180.86 35.3 270 top
RN2412  SRN100KJ-5-GP  [ARES8-CN24H20]  189.94 43.88 0 bottom
RN2602  SRN2K2J-1-GP  [ARES2H16]  139.85 22.75 0 top
RN2604  SRN2K2J-1-GP  [ARES2H16]  175.56 29.94 270 top
RN2701  SRN1KJ-7-GP  [SMD-ARES4H18]  31.8 12.54 0 bottom
RN2901  SRN2K2J-1-GP  [ARES2H16]  16.78 18.5 90 top
RN3701  SRN2K2J-1-GP  [ARES2H16]  36.5 43.78 90 top
RN3702  SRN2K2J-1-GP  [ARES2H16]  33.2 35.09 90 top
RN4302  SRN100J-4-GP  [ARES8-CN24H20]  163.7 25.92 180 top
RN5501  SRN100J-4-GP  [ARES8-CN24H20]  96.82 94.45 0 top
RN5502  SRN100KJ-5-GP  [ARES8-CN24H20]  99.79 99.08 90 top
RN5503  SRN33J-5-GP-U  [SMD-ARES4H18]  61.29 90.24 90 top
RN6501  SRN10KJ-5-GP  [ARES2H18]  124.26 3.78 180 top
RN6502  SRN33J-5-GP-U  [SMD-ARES4H18]  125.91 3.78 0 top
RN6503  SRN2K2J-1-GP  [ARES2H16]  129.97 3.9 0 top
RN7001  SRN0J-6-GP  [SMD-ARES4H20]  116.97 22.29 90 bottom
SPI25  MX25L12873FM2I-10G-GP  [SOIC8-1H86]  128.7 17.54 0 bottom
SPK1  HR-CON6-1-GP-U  [A1001WR-S06PN6BT1TS2R-U]  12.7 5.14 180 bottom
SPR1  SPRING-171-GP  [SPR5128H111]  116.7 92.71 0 top
SPR2  SPRING-171-GP  [SPR5128H111]  89.7 53.71 0 top
SPR3  SPRING-171-GP  [SPR5128H111]  41.7 19.71 0 top
SPR4  SPRING-7-GP  [SPR6438H83]  117.85 91.71 0 bottom
SSD1  SKT-MINI67P-15-GP  [AS0BC2Y-S30BM-7H]  200.1 22.19 270 bottom
TCBD1  JAE-CON32-2-GP-U  [FL10F032HA2R3000]  62.9 96.91 0 bottom
THM261  NCT7718W-GP  [MSOP8-1H44]  137.56 25.42 270 bottom
TP1  ACES-CON8-66-GP  [51574-0084N-W01]  126.9 7.21 180 bottom
TP401  TPAD14-OP-GP  [TPAD14-OP]  124.48 73.09 270 top
TP402  TPAD14-OP-GP  [TPAD14-OP]  129.69 77.69 270 bottom
TP403  TPAD14-OP-GP  [TPAD14-OP]  127.2 37.35 90 top
TP404  TPAD14-OP-GP  [TPAD14-OP]  104.57 37.66 180 top
TP405  TPAD14-OP-GP  [TPAD14-OP]  127.48 68.5 270 top
TP406  TPAD14-OP-GP  [TPAD14-OP]  126.46 67.73 270 top
TP407  TPAD14-OP-GP  [TPAD14-OP]  125.5 66.87 270 top
TP408  TPAD14-OP-GP  [TPAD14-OP]  129.39 68.95 270 bottom
TP409  TPAD14-OP-GP  [TPAD14-OP]  126.03 39.34 0 top
TP601  TPAD14-OP-GP  [TPAD14-OP]  103.45 76.52 90 top
TP602  TPAD14-OP-GP  [TPAD14-OP]  99.74 76.14 90 top
TP603  TPAD14-OP-GP  [TPAD14-OP]  99.95 77.36 90 top
TP604  TPAD14-OP-GP  [TPAD14-OP]  98.7 77.39 90 top
TP607  TPAD14-OP-GP  [TPAD14-OP]  106.22 39.21 90 top
TP608  TPAD14-OP-GP  [TPAD14-OP]  107.7 39.97 90 top
TP609  TPAD14-OP-GP  [TPAD14-OP]  103.3 38.4 90 top
TP610  TPAD14-OP-GP  [TPAD14-OP]  102.44 37.23 90 top
TP611  TPAD14-OP-GP  [TPAD14-OP]  101.14 37.89 90 top
TP612  TPAD14-OP-GP  [TPAD14-OP]  123.24 73.09 90 top
TP613  TPAD14-OP-GP  [TPAD14-OP]  121.92 73.07 90 top
TP614  TPAD14-OP-GP  [TPAD14-OP]  103.02 75.35 90 top
TP615  TPAD14-OP-GP  [TPAD14-OP]  100.99 76.67 90 top
TP616  TPAD14-OP-GP  [TPAD14-OP]  108.58 68.75 0 top
TP617  TPAD14-OP-GP  [TPAD14-OP]  109.88 68.95 90 top
TP618  TPAD14-OP-GP  [TPAD14-OP]  126.03 75.71 90 top
TP619  TPAD14-OP-GP  [TPAD14-OP]  125.93 76.93 90 top
TP620  TPAD14-OP-GP  [TPAD14-OP]  127.25 76.01 90 top
TP621  TPAD14-OP-GP  [TPAD14-OP]  126.11 74.46 90 top
TP622  TPAD14-OP-GP  [TPAD14-OP]  123.34 77.82 90 top
TP623  TPAD14-OP-GP  [TPAD14-OP]  124.86 77.56 90 top
TP624  TPAD14-OP-GP  [TPAD14-OP]  123.77 76.67 90 top
TP625  TPAD14-OP-GP  [TPAD14-OP]  124.76 74.59 180 top
TP626  TPAD14-OP-GP  [TPAD14-OP]  123.34 80.31 0 top
TP627  TPAD14-OP-GP  [TPAD14-OP]  121.05 80.94 0 top
TP628  TPAD14-OP-GP  [TPAD14-OP]  123.32 79.06 0 top
TP629  TPAD14-OP-GP  [TPAD14-OP]  123.32 81.68 0 top
TP630  TPAD14-OP-GP  [TPAD14-OP]  122.25 79.72 0 top
TP631  TPAD14-OP-GP  [TPAD14-OP]  122.3 80.97 0 top
TP632  TPAD14-OP-GP  [TPAD14-OP]  121 79.7 0 top
TP633  TPAD14-OP-GP  [TPAD14-OP]  121.61 82.06 0 top
TP634  TPAD14-OP-GP  [TPAD14-OP]  123.87 72.03 0 top
TP635  TPAD14-OP-GP  [TPAD14-OP]  122.6 72.05 0 top
TP636  TPAD14-OP-GP  [TPAD14-OP]  123.77 75.33 0 top
TP637  TPAD14-OP-GP  [TPAD14-OP]  122.55 75.43 0 top
TP638  TPAD14-OP-GP  [TPAD14-OP]  124.71 40.25 0 top
TP701  TPAD14-OP-GP  [TPAD14-OP]  121.69 53.79 0 top
TP707  TPAD14-OP-GP  [TPAD14-OP]  110.36 55.21 0 top
TP801  TPAD14-OP-GP  [TPAD14-OP]  125.47 65.65 0 top
TP1602  TPAD14-OP-GP  [TPAD14-OP]  122.6 33.11 0 top
TP1603  TPAD14-OP-GP  [TPAD14-OP]  122.78 34.43 0 top
TP1605  TPAD14-OP-GP  [TPAD14-OP]  129.54 67.68 180 bottom
TP1606  TPAD14-OP-GP  [TPAD14-OP]  123.55 70.83 0 top
TP1703  TPAD14-OP-GP  [TPAD14-OP]  101.09 44.97 270 top
TP1704  TPAD14-OP-GP  [TPAD14-OP]  102.49 44.57 270 top
TP1705  TPAD14-OP-GP  [TPAD14-OP]  133.35 78.81 270 bottom
TP1706  TPAD14-OP-GP  [TPAD14-OP]  107.7 46.37 270 top
TP1707  TPAD14-OP-GP  [TPAD14-OP]  106.02 43.27 270 top
TP1708  TPAD14-OP-GP  [TPAD14-OP]  108.9 43.68 270 top
TP1709  TPAD14-OP-GP  [TPAD14-OP]  125.88 37.1 0 top
TP1710  TPAD14-OP-GP  [TPAD14-OP]  99.34 45.71 0 top
TP1711  TPAD14-OP-GP  [TPAD14-OP]  108.98 45.43 0 top
TP1802  TPAD14-OP-GP  [TPAD14-OP]  121.84 61 0 top
TP1803  TPAD14-OP-GP  [TPAD14-OP]  123.29 61.03 0 top
TP1804  TPAD14-OP-GP  [TPAD14-OP]  116.18 33.04 0 top
TP1805  TPAD14-OP-GP  [TPAD14-OP]  117.55 33.19 0 top
TP1806  TPAD14-OP-GP  [TPAD14-OP]  119.51 32.45 0 top
TP1808  TPAD14-OP-GP  [TPAD14-OP]  92.9 37.39 0 top
TP1902  TPAD14-OP-GP  [TPAD14-OP]  101.06 40.25 0 top
TP1906  TPAD14-OP-GP  [TPAD14-OP]  121.82 39.97 0 top
TP2006  TPAD14-OP-GP  [TPAD14-OP]  118.57 33.9 270 top
TP2007  TPAD14-OP-GP  [TPAD14-OP]  113.66 41.55 0 top
TP2012  TPAD14-OP-GP  [TPAD14-OP]  117.41 34.57 270 top
TP2013  TPAD14-OP-GP  [TPAD14-OP]  116.1 34.26 270 top
TP2014  TPAD14-OP-GP  [TPAD14-OP]  116.89 39.11 270 top
TP2016  TPAD14-OP-GP  [TPAD14-OP]  112.98 34.15 270 top
TP2017  TPAD14-OP-GP  [TPAD14-OP]  114.81 32.94 270 top
TP2020  TPAD14-OP-GP  [TPAD14-OP]  110.93 34 270 top
TP2027  TPAD14-OP-GP  [TPAD14-OP]  116.91 40.35 0 top
TP2028  TPAD14-OP-GP  [TPAD14-OP]  116.84 41.6 0 top
TP2101  TPAD14-OP-GP  [TPAD14-OP]  108.98 41.8 0 top
TP2102  TPAD14-OP-GP  [TPAD14-OP]  107.7 42.71 0 top
TP2301  TPAD14-OP-GP  [TPAD14-OP]  102.23 76.67 0 top
TP2302  TPAD14-OP-GP  [TPAD14-OP]  101.55 75.51 0 top
TP2303  TPAD14-OP-GP  [TPAD14-OP]  104.7 76.75 0 top
TP2304  TPAD14-OP-GP  [TPAD14-OP]  105.92 76.67 0 top
TP2305  TPAD14-OP-GP  [TPAD14-OP]  99.74 36.06 0 top
TP2306  TPAD14-OP-GP  [TPAD14-OP]  100.1 37.25 0 top
TP2307  TPAD14-OP-GP  [TPAD14-OP]  106.25 35.7 0 top
TP2308  TPAD14-OP-GP  [TPAD14-OP]  129.59 37.74 180 bottom
TP2309  TPAD14-OP-GP  [TPAD14-OP]  130.78 38.32 180 bottom
TP2310  TPAD14-OP-GP  [TPAD14-OP]  124.89 78.83 0 top
TP2311  TPAD14-OP-GP  [TPAD14-OP]  126.01 78.17 0 top
TP2312  TPAD14-OP-GP  [TPAD14-OP]  124.81 76.04 0 top
TP2313  TPAD14-OP-GP  [TPAD14-OP]  122.25 78.45 0 top
TP2402  TPAD14-OP-GP  [TPAD14-OP]  193.8 42.18 180 bottom
TP2405  TPAD14-OP-GP  [TPAD14-OP]  181.13 40.78 0 top
TP2406  TPAD14-OP-GP  [TPAD14-OP]  196.9 44.31 180 bottom
TP2407  TPAD14-OP-GP  [TPAD14-OP]  200.71 30.7 0 top
TP2702  TPAD14-OP-GP  [TPAD14-OP]  29.39 13.3 180 top
TP3703  TPAD14-OP-GP  [TPAD14-OP]  27.23 34.89 90 top
U3401  TPS2544RTER-GP  [QFN16-G1D8-UH32]  22.35 46.45 0 bottom
U3501  SY6288DAAC-GP  [SOT-23-5H56]  22.66 38.57 90 bottom
U3701  CYPD4125-40LQXIT-8-GP  [QFN40G6-G4D7H24]  30.05 42.51 90 top
U3702  TPS70933DRVR-GP-U  [DFN6F2-G1711-UH32]  27.46 94.02 270 top
U3703  AP2151DFMG-7-GP-U  [DFN6G1820-G1511-UH24]  24.61 38.62 180 top
U3801  TUSB546-DCIRNQR-GP  [QFN40J4060-G2848H32]  33.7 59.15 180 top
U3802  TS3DS10224RUKR-GP  [QFN20J3-G1D8H32]  41.81 35.83 180 top
U4001  TPS22976DPUR-GP  [SON14J3020-G2610H34]  134.29 102.07 270 bottom
U4002  G5027RD1D-GP-U  [DFN8F3-G2517H32]  91.97 91.36 90 top
U4003  U74LVC1G08G-AL5-R-GP-U  [SC70-5-1H44]  129.87 99.76 90 bottom
U4006  G5027RD1D-GP-U  [DFN8F3-G2517H32]  108.51 16.53 270 bottom
U4302  S-1004NA23I-M5T1U-GP  [SOT-23-5H52]  22.66 81.58 90 bottom
U5501  RT9724GB-GP  [SOT-23-5H51]  81.79 98.19 90 top
U5701  PS8201ATQFN40GTR2-A0-GP  [QFN40J5-G3D65H32]  23.29 65.84 270 top
U6001  AZ1045-04F-R7G-GP  [DFN10G2510H26]  174.42 13.94 270 top
U6002  APE8937GN2-GP-U  [DFN8G2-G1710-U1H32]  174.67 17.42 90 top
U6301  AZ1043-04F-R7G-GP  [DFN10G2510H22]  188.92 14.85 270 top
U6302  AZ1043-04F-R7G-GP  [DFN10G2510H22]  195.77 19.14 0 top
U6303  AZ1043-04F-R7G-GP  [DFN10G2510H22]  198.68 14.82 0 top
U6304  AZ1043-04F-R7G-GP  [DFN10G2510H22]  193.32 11.83 270 top
U7001  LNG2DMTR-GP  [LGA12G2H40]  177.16 42.76 270 top
U9104  NPCT650VB2YX-GP  [QFN32G5-G3D6H32]  38.53 28.03 90 top
USB1  SKT-USB34-21-GP-U  [SKT-USB34-124103-U]  2.19 94.21 90 bottom
USB2  SKT-USB13-221-GP  [SKT-USB13-160162-2]  6.5 53.03 90 bottom
USB3  SKT-USB13-221-GP  [SKT-USB13-160162-2]  6.5 32.43 90 bottom
X1801  XTAL-24MHZ-87-GP  [OSC-3225-4P-4H30]  134.14 50.84 270 bottom
X1802  XTAL-32D768KHZ-91-GP  [SMD49-3215-0713H36]  103.35 23.16 90 bottom
X2201  XTAL-24MHZ-87-GP  [OSC-3225-4P-4H30]  134.97 37.18 270 bottom
X2401  XTAL-32D768KHZ-91-GP  [SMD49-3215-0713H36]  201.42 26 180 top

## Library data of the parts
AFTP225 AFTP2601-AFTP2604 AFTP2901-AFTP2904 AFTP4301-AFTP4315 AFTP6302-AFTP6304 AFTP6501-AFTP6524 AFTP6529-AFTP6539 = AFTE14P-75: tolerance: ZZ.AFT14.101
BATT1 = 50299-01001-002-U: tolerance: 20.F2460.010
C715 C1120 C1123 C1202-C1206 C1208-C1210 C1303-C1310 C1324 C1325 C1704 C2601 C2702 C2706 C2708 C2712 C2713 C2718 C2902 C2907 C2908 C3513 C3514 C3718 C4006 C4009 C4012 C4013 C5520 C7004 PC1107-PC1109 PC5402 PC5412 PC5413 = C603H38: tolerance: 78.10610.5BL
C716 C717 C719 C1101-C1111 C1114 C1116 C1117 C1119 C1121 C1124-C1127 C1214-C1221 C1225 C1226 C1315-C1322 C1326 C1327 C1805 C1806 C2101-C2109 C2116 C2117 C2120 C2121 C2418 C2714 C3401 C3508 C3703 C3704 C3715 C3722 C3815 C3816 C3818 C4031-C4034 C5508 EC1005 PC4428 PC4431 PC4438 = C402H22: tolerance: 78.10523.5FL
C718 C720 C721 C1229 C1301 C2110-C2112 C2118 C2406-C2408 C2410-C2416 C2420-C2423 C2428 C2429 C2602 C2605 C2612 C2701 C2707 C2709 C2710 C2717 C2719 C2720 C2722 C3402 C3403 C3502 C3507 C3721 C3723 C4007 C5507 C5703 C5704 C5706 C5713 C5716 C6002 C6501-C6503 C7002 C7003 C9102 PC4513 PC4518 PC4528 PC5102 PC5116 PC5118-PC5120 PC5138 PC5407 PC5427 = C402H22: tolerance: 78.10421.2FLDL
C1112 C1113 C1115 C1118 C1122 C2113-C2115 C2119 C2122 C3404 C3405 C6317 C6318 PC1001-PC1083 PC1085 PC1101-PC1106 PC1114 PC1115 PC5114 PC5201 PC5203 PC5205 PC5206 = C603H40: tolerance: 78.22610.5BL
C1207 C1211-C1213 C1223 C1224 C1227 C1230-C1232 C1311-C1314 C1330 C1331 C6004 C6009 PC4631 PC4708 PC4728 PC4808 PC5110 PC5111 PC5202 PC5401 PC5408-PC5410 = C402H22: tolerance: 78.10523.5FLDL
C1222 C1323 = C402H22: tolerance: 78.22321.2FL
C1228 C1328 = C402H22: tolerance: 78.10421.L0L
C1329 R1216 = C603H36: tolerance: 78.22523.L1L
C1601 C1602 C3601-C3604 C5501 C5504 C5506 C5509-C5511 C5519 C5531-C5533 C5707-C5712 C5714 C5715 = C402H22: tolerance: 78.10421.2FLDL; signal model: 2pins
C1605-C1612 C6302 C6303 C6311-C6316 = C402H22: tolerance: 78.22423.5FL; signal model: 2pins
C1701 EC6401 EC6402 = C402H22: tolerance: 78.22124.2FL
C1710 = C402H22: tolerance: 78.47423.5FL
C1711 C2409 PC4303-PC4305 = C402H22: tolerance: 78.10324.2FL
C1801 C1802 C2201 C2202 = C402H22: tolerance: 78.15034.1FL
C1803 C1804 = C402H24: tolerance: 78.9R064.1FL
C2405 C2613 EC2901-EC2908 EC6505-EC6530 PC4310 PC4311 PC4315 = C402H22: tolerance: 78.10134.1FL
C2424 C2425 = C402H22: tolerance: 78.18034.1FLDL
C2426 C3819 PC4524 PC4707 PC4721 PC4807 PC5001 PC5113 = C603H36: tolerance: 78.22523.5BLDL
C2435 C2436 C2441 C2603 C2607 C9101 C9104 EC8906 EC8933-EC8935 PC4403 PC4404 PC4410 PC4421 PC4422 PC4424 PC4430 PC4434 PC4810 = C402H22: tolerance: 78.22224.2FL
C2501 = C805H54: tolerance: 78.10623.51L
C2502 C2608-C2610 C2721 C3503 C3701 C3702 C3705 C3709 C3716 C3717 C3719 C3817 C3820 C3865 C4008 C6007 C6008 C6010 C6307 C6504 C9113 EC1707 EC1712 EC1806 EC1807 EC1902 EC2504 = C402H22: tolerance: 78.10421.2FL
C2503 = C603H36: tolerance: 78.47422.5BLDL
C2604 C2711 C2715 C2716 C2724 C5502 C5503 C5505 C5515 C5517 C9105 C9106 C9114 = C603H36: tolerance: 78.47520.5BL
C2606 = C603H36: tolerance: 78.47134.1BL
C2703 C2704 C3707 EC8905 EC8927-EC8929 PC4301 = C603H32: tolerance: 78.10524.5BL
C2705 C3710 = C603H36: tolerance: 78.22523.5BL
C2723 C6304 C6305 EC2701 EC2708 EC2709 EC5505 EC6501-EC6504 EC6601-EC6603 = C402H22: tolerance: 78.33034.1FL
C3406 C4004 C4005 C5701 C5702 PC5115 PC5403 PC5414 = C603H36: tolerance: 78.10610.5BLDL
C3407 EC2909-EC2912 PC4307 PC4526 PC4533 PC4603 PC4605 PC4608 PC4611 PC4625 PC4627 PC4632 PC4633 PC5215 = C402H22: tolerance: 78.10224.2FLDL
C3512 = C805H58: tolerance: 78.22610.51L
C3711 C3712 = C402H24: tolerance: 78.39124.2FL
C3720 C4010 C4011 = C402H22: tolerance: 78.22423.5FL
C3801-C3814 C3861-C3864 = C402H22: tolerance: 78.10421.2FL; signal model: 2pins
C3821 EC2101 EC2703 EC2705 EC4302 EC4307 EC4534 EC4701 EC4801 EC5001 EC5502 EC8901 EC8903 EC8907-EC8917 EC8919-EC8925 EC8930-EC8932 EC8936-EC8955 PC1110-PC1113 PC4312 PC4313 PC4402 PC4409 PC4411 PC4419 PC4420 = C402H22: tolerance: 78.10422.5FL
C4001 C4002 = C402H22: tolerance: 78.47124.2FL
C5512 C5516 C5542 EC4308 PC4302 PC4416 = C603H36: tolerance: 78.10424.2BL
C5513 C5534 EC1706 EC2002 EC2704 EC2706 EC2707 EC8902 EC8904 EC8918 PC4436 PC4437 = C402H22: tolerance: 78.10224.2FL
C5514 C5518 = C603H40: tolerance: 078.22529.05B1
C5705 C5717 = C402H22: tolerance: 78.10134.1FLDL
C6001 C6003 C6005 C6006 = C402H22: tolerance: 78.10324.2FL; signal model: 2pins
C6306 C6308 = C402H22: tolerance: 78.47322.2FL
C7001 = C402H22: tolerance: 78.47321.2FL
CPU1 = BGA1356M4224-U2H52: tolerance: 071.SKYLA.000U
D1701 D2402 D2403 D4002 PD4305 PD4306 PD4409 PD4411 = SOD323AKH38: tolerance: 83.R2004.G8F
D2501 = SOT-23-9H44: tolerance: 75.00040.07D
D2601 = SOD323AKH38: tolerance: 83.R5003.H8H
D2701 D5501-D5503 = SOT23-2D4-312H44: tolerance: 75.00054.T7D
D3701 D3702 = D1006-0305AK-UH22: tolerance: 083.00520.0F8F
D4001 = SOT23-2D4-312H44: tolerance: 83.00016.P11
D4304-D4306 PD4302 = SOT23-2D4-312H44: tolerance: 75.00099.O7D
D5701 = SOT23-2D4-312H44: tolerance: 83.00056.Y11
D7001 = SOT23-2D4-312H48: tolerance: 75.00054.R7D
DB1 = 87212-1400N: tolerance: 20.F0765.014
DB3 = 50696-00601-001: tolerance: 20.K0691.006
DCIN1 = 50224-0080N-W02-U: tolerance: 20.F1295.008
DM1 = ADDR0206-P013A: tolerance: 062.10011.01C1
DM2 = ADDR0205-P012A: tolerance: 062.10011.01B1
EC1001-EC1004 EC1006 EC1007 = C402H22: tolerance: 78.10422.L1L
EC1102 EC1103 EC1202 EC1302 EC1303 EC1710 EC1713 EC4425 EC8926 PC4413 = C402H22: tolerance: 78.22523.5FL
EC1803 EC2501 EC2502 = C402H22: tolerance: 78.4R7B4.1FL
EC1804 EC1901 EC2503 EC4306 EC4309 EC4310 = C402H22: tolerance: 78.10034.1FL
EC4301 PC4306 PC4417 PC4502-PC4505 PC4519 PC4523 = C603H40: tolerance: 78.10612.5BL
EC5501 = C402H22: tolerance: 78.6R864.1FL
EC5503 EC5504 = C402H22: tolerance: 78.22034.1FL
ED401 ED501 ED1217 ED1302 ED1701-ED1705 ED1708 ED1709 ED1711 ED2401 ED2902-ED2905 = SOD882-10D6-1H20: tolerance: 83.05725.0A0
ED2901 ED2906 = D1608AK-UH28: tolerance: 75.0DF2B.077
ED3601 ED3603 ED3802 ED3806 = SLP2510P8-1H22: tolerance: 075.00550.0071
ED3602 = SOT-6H58: tolerance: 75.09904.07C
ED3801 ED3803-ED3805 = SOT883-1D0-321H20: tolerance: 83.05315.0A0
ED6305 = SOD882-10D6-1H20: tolerance: 83.0005V.CAF
ED6401 ED6402 = SOD-523-2H26: tolerance: 83.0005V.0AF
EL2901-EL2904 = L402H24: tolerance: 68.00358.031
EL3605 EL3606 EL5501 EL5502 EL6601-EL6603 = L125100-4P-4H24: tolerance: 68.00396.001
EL3801 EL3802 = L125100-4P-4H24: tolerance: 68.00396.001; signal model: 4pins1
EL4301-EL4304 = R805H24: tolerance: 63.R0031.16L
F5501 F5502 F5504 F5701 F6501 = POLYSW-2114H30: tolerance: 69.48001.081
F5503 = POLYSW-4633-UH43: tolerance: 69.50007.A31
FAN1 = 50224-0040N-001: tolerance: 20.F1639.004
G1801 = CON2O-U: tolerance: ZZ.CON2O.XXX
GMR1 = OPLGA4-0913H22: tolerance: 074.00013.00BJ
GPU1 = XBGCB5009-U2: tolerance: 020.F0581.0048
GPU2 = XBGCB5008: tolerance: 020.F0588.0028
H2 H4 H7-H10 = HOLE335R178: tolerance: ZZ.00PAD.7F1
H3 H5 H6 = HOLE335R229: tolerance: ZZ.00PAD.7G1
HDA27 = QFN48J6-G465H40: tolerance: 071.03253.0A03
HDD1 = GS12201-1011-9H: tolerance: 20.F1546.020
HDMI1 = SKT-HDMI23-188137-4: tolerance: 022.10025.00M1
HPMIC1 = AJ3R2D-Y050-412: tolerance: 022.10002.00D1
HS1 = STF217R115H101: tolerance: 434.04X0C.1001
HS2 HS3 = STFSR158R113H62: tolerance: 434.07R01.0001
IOBD1 = 20455-050E-76: tolerance: 020.F0574.0050
KB1 = 196528-30041-3: tolerance: 020.K0210.0030
KBBL1 = 50698-00401-W01-U: tolerance: 020.K0298.0004
KBC24 = TQFP128-2H48: tolerance: 071.01416.000G
L3801 = L402H22: tolerance: 068.00006.0141
LCD1 = 20455-040E-12: tolerance: 20.F1407.040
LED1 = 50524-00401-001: tolerance: 020.K0037.0004
PC4314 = C402H22: tolerance: 78.10522.5FL
PC4405-PC4408 PC4415 PC4418 PC4433 PC4435 = C805H56: tolerance: 78.10622.51L
PC4412 = C603H36: tolerance: 078.10524.05BD
PC4414 PC4426 = C603H40: tolerance: 78.22422.2BL
PC4423 PC4612 PC4618 PC4647 PC4648 PC4709 PC4727 PC5031 = C402H22: tolerance: 78.22224.2FLDL
PC4427 = C402H24: tolerance: 78.56124.2FL
PC4432 = C402H22: tolerance: 78.22321.2FLDL
PC4501 PC4506 PC4508 PC4521 PC4522 PC4530-PC4532 PC4610 PC4628 PC4630 PC4710 PC4730 PC4811 PC5002 PC5117 PC5204 PC5208 = C402H22: tolerance: 78.10422.5FLDL
PC4507 PC4520 = C805H54: tolerance: 78.47522.51LDL
PC4509-PC4512 PC4514-PC4517 PC4525 PC4527 PC4529 PC5101 PC5103-PC5105 = C603H40: tolerance: 78.22610.5BLDL
PC4601 = C402H22: tolerance: 78.15224.2FLDL
PC4602 PC4616 PC4634 = C402H22: tolerance: 78.15322.2FLDL
PC4604 PC4619 = C402H22: tolerance: 78.15034.1FLDL
PC4606 PC4607 PC4629 PC4646 PC5107 PC5213 = C402H22: tolerance: 78.10324.2FLDL
PC4609 PC5212 = C402H22: tolerance: 78.22124.2FLDL
PC4613-PC4615 PC4620 = C402H22: tolerance: 78.47124.2FLDL
PC4617 = C402H22: tolerance: 78.10034.1FLDL
PC4621 PC5112 = C402H22: tolerance: 78.33124.2FLDL
PC4622 = C402H22: tolerance: 78.33224.2FLDL
PC4623 PC4641 = C402H22: tolerance: 078.47322.02FD
PC4702-PC4705 PC4723-PC4726 PC4729 PC4802-PC4806 PC5027 PC5029 PC5106 PC5108 PC5209-PC5211 PC5216 = C805H58: tolerance: 78.10622.51LDL
PC4706 PC4722 PC4809 PC5008 = C603H36: tolerance: 78.22422.2BLDL
PC5214 = C603H35: tolerance: 78.10424.2BLDL
PC5405 PC5411 = C402H22: tolerance: 78.68034.1FL
PC5406 = C402H22: tolerance: 78.47224.2FL
PD4301 = D4724AKH44: tolerance: 083.00624.00AM
PD4303 = SOT23-2D4-312H60: tolerance: 83.03024.0A1
PD4304 = SOD123AK-2H43: tolerance: 83.SMF18.AAH
PD4307-PD4310 = SOD923-10D6AKH18: tolerance: 83.BAT54.A8F
PD4401 PD4402 PD4405-PD4407 = SOD323-2513AKH36: tolerance: 83.R2004.J8F
PD4404 = SOD323AKH44: tolerance: 83.00355.G1F
PG4401 PG4404-PG4408 PG4414 PG4415 PG4419 PG4501-PG4524 PG4527-PG4532 PG4601 PG4701-PG4705 PG4707 PG4708 PG4711 PG4712 PG4721-PG4723 PG4808 PG4809 PG5001 PG5002 PG5021 PG5022 PG5101-PG5104 PG5106-PG5115 PG5120 PG5121 PG5201 PG5204 PG5206-PG5216 PG5404-PG5409 = GAP-CLOSE-PWR-3: tolerance: ZZ.CLOSE.001
PG4402 PG4403 PG4409 PG4410 PG4412 PG4413 PG5223 = GAP-CLOSE-PWR: tolerance: ZZ.CLOSE.011
PL4401 = L7066-1830-UH119: tolerance: 68.4R71A.20H
PL4501 = L4947-1015H119: tolerance: 68.1R550.20C
PL4502 = L7066-1830-UH119: tolerance: 68.2R210.20B
PL4701 PL4702 PL4801 = L7366-1930H158: tolerance: 68.R1510.20A
PL5001 = L7066-1830-UH119: tolerance: 68.R4710.10M
PL5101 = L4947-1115H119: tolerance: 68.1R010.20R
PL5201 = L686647-127318H119: tolerance: 68.1R01B.10K
PQ4301 Q501 Q6403 = SOT23DGS2D4H44: tolerance: 084.00138.0A31
PQ4302 Q2603 = SOT-23-10H44: tolerance: 84.03904.L06
PQ4304 = SOT323CBE2D2H40: tolerance: 84.05212.B11
PQ4305 = SC70-2D2-312H44: tolerance: 84.00024.01K
PQ4306 PQ4312 Q2408 Q2414 Q2415 Q2417 Q2602 Q2701 Q3701 Q6503 = SOT23DGS2D4H44: tolerance: 84.2N702.J31
PQ4307-PQ4311 PQ4313 PQ4405 PQ4415 Q1702 Q2416 Q2503 Q5704 Q7001 = SOT-363H44: tolerance: 75.27002.F7C
PQ4408 = SOT-23-10H44: tolerance: 84.03906.F11
PR2455 PR4433 = R402H16: tolerance: 64.15035.6DL
PR4302 = R402H16: tolerance: 64.15025.6DL
PR4303 PR5410 R802 R1503 R1606-R1608 R1701 R1707 R1714 R1726 R1739 R1820 R1821 R1827 R1828 R1912-R1921 R2001 R2005 R2008-R2010 R2029 R2030 R2040-R2047 R2050 R2415 R2429-R2431 R2473 R2607 R2726 R2919 R2920 R3402 R3405 R3406 R3738 R3818 R4009 R6120 R6303 R6304 R6511 R7005 R7006 R9119 R9120 R9131 R9140 R9141 R9148 = R402H16: tolerance: 63.10334.1DL
PR4304 PR4328 R1836 R2717 R2912 R2913 R3707 R5706 R5707 = R402H16: tolerance: 63.22234.1DL
PR4305 PR4306 R9132 R9134 R9139 = R402H16: tolerance: 63.33034.1DL
PR4307 = R603H22: tolerance: 63.24434.15L
PR4308 PR4321 R1719 R2517 = R402H16: tolerance: 64.47025.6DL
PR4309 PR4318 PR4335 PR4431 PR4505 PR4510 PR5208 R404 R603 R803 R1715 R1717 R1727 R1737 R2031-R2036 R2417 R2434 R2436 R2449-R2451 R2454 R2480 R2489 R2496 R2509 R2711 R2722 R2728 R3501 R3734 R3739 R3801 R3802 R4031 R4032 R5721 R6306 R6508 R6509 R7001 R7011 R7018 = R402H16: tolerance: 63.10434.1DL
